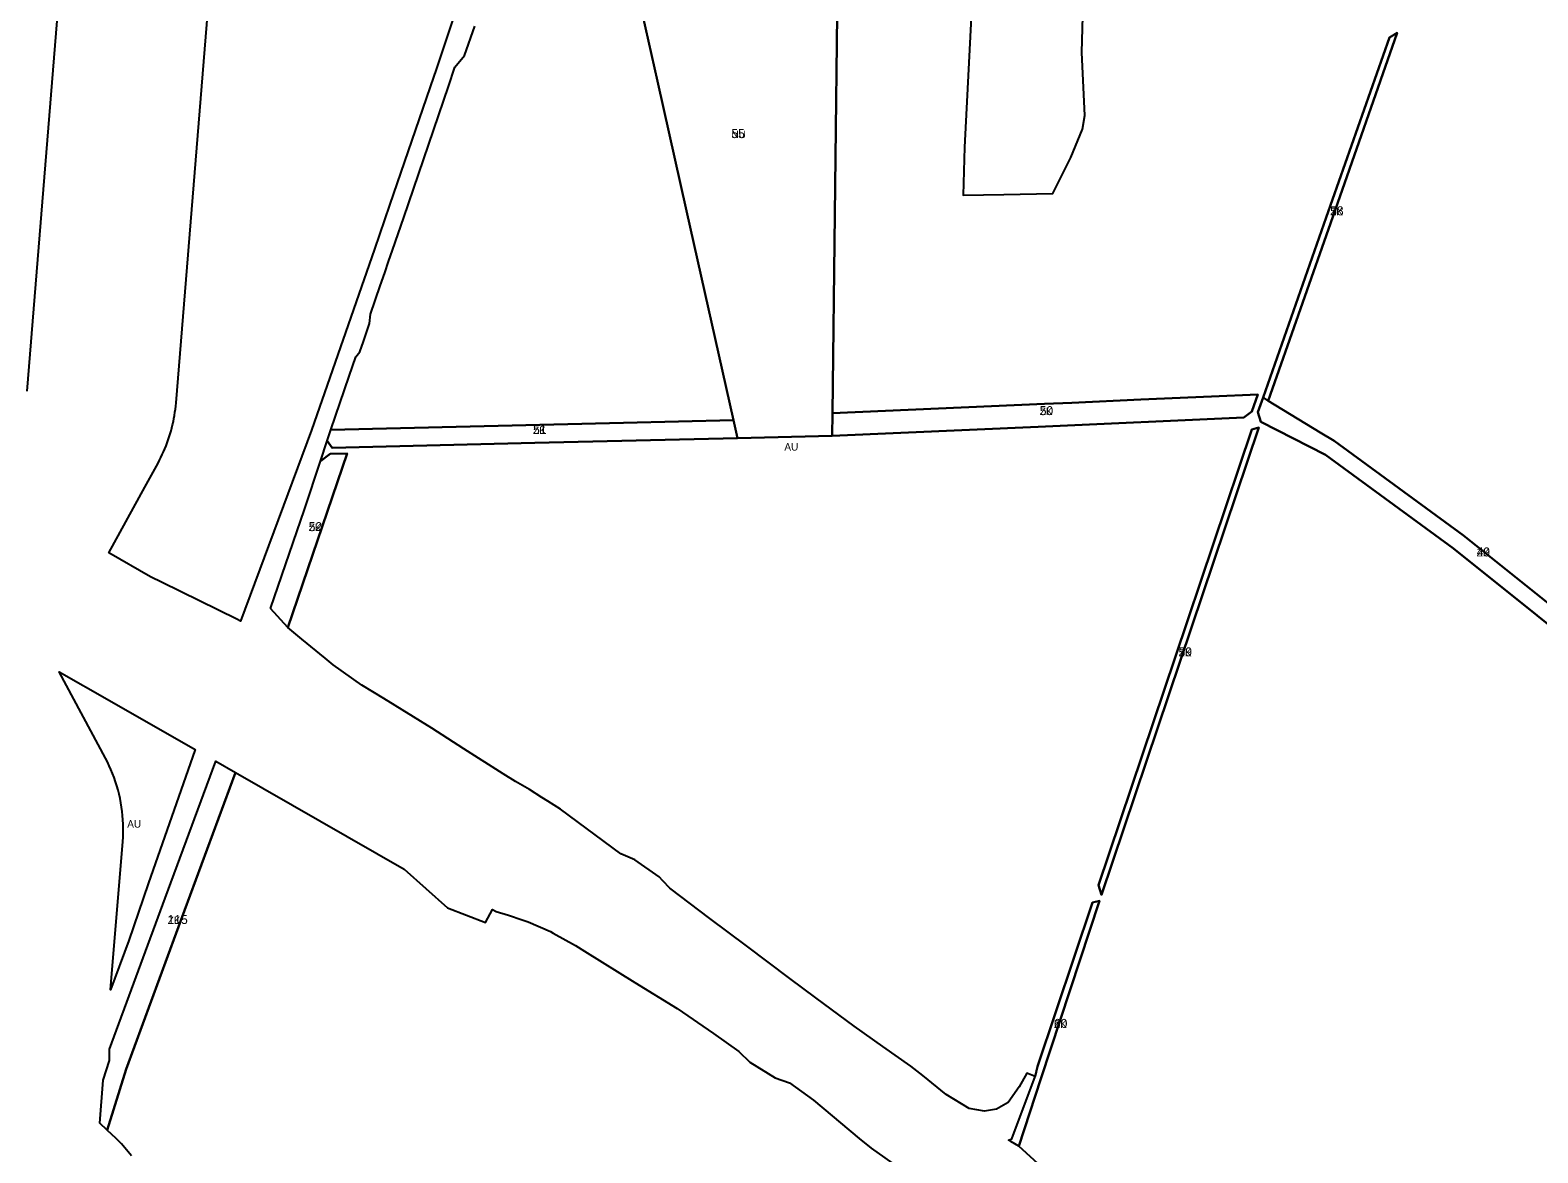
# Model space of a CAD drawing. Extents: x -545779 to -541342, y -1153413 to -1149956.
# Drawn here: x -544840 to -543834, y -1152759 to -1152010 of the extents above; entities that cross this region are included whole.
import ezdxf

# ---------------------------------------------------------------- set-up
doc = ezdxf.new("R2010")
doc.units = 0
for name, color, linetype in [('90710023', 7, 'Continuous'), ('90730023', 7, 'Continuous'), ('90750013', 7, 'Continuous'), ('ID_navrh', 7, 'Continuous')]:
    doc.layers.add(name, color=color, linetype=linetype)

msp = doc.modelspace()

# ---------------------------------------------------------------- linework, layer by layer
at = {"layer": '90710023'}
for points in [[(-543974.76, -1152134.86), (-543974.76, -1152134.86), (-543932.62, -1152014.61), (-543927.33, -1152011.63), (-543970.37, -1152134.42), (-544013.41, -1152257.22), (-544016.91, -1152255.1)], [(-544167.08, -1152274.5), (-544167.08, -1152274.5), (-544304.43, -1152280.58), (-544304.26, -1152265.56), (-544162.8, -1152259.29), (-544144.44, -1152258.48), (-544098.47, -1152256.44), (-544051.35, -1152254.35), (-544020.4, -1152252.98), (-544024.42, -1152264.45), (-544029.74, -1152268.41)], [(-544502.79, -1152285.35), (-544638.01, -1152288.6), (-544641.43, -1152283.98), (-544638.99, -1152276.62), (-544443.74, -1152271.92), (-544370.25, -1152270.16), (-544367.57, -1152282.1)], [(-544075.6, -1152428.52), (-544024.37, -1152276.35), (-544019.71, -1152275.05), (-544072.24, -1152431.07), (-544124.76, -1152587.09), (-544126.82, -1152580.69)], [(-544679.3, -1152395.86), (-544656.61, -1152329.75), (-544645.92, -1152297.5), (-544639.34, -1152292.63), (-544628.21, -1152292.37), (-544667.8, -1152408.57)], [(-544790.854, -1152710.719), (-544786.64, -1152697.75), (-544786.7, -1152690.05), (-544749.46, -1152589.25), (-544715.712, -1152497.902), (-544702.513, -1152505.459), (-544736.56, -1152597.62), (-544775.66, -1152703.45), (-544788.338, -1152744.096), (-544793.194, -1152739.453)], [(-544167.53, -1152701.6), (-544130.71, -1152592.24), (-544126.11, -1152591.11), (-544165.26, -1152709.92), (-544179.87, -1152754.91), (-544185.3, -1152751.8), (-544186.78, -1152750.95), (-544184.48, -1152749.94), (-544168.92, -1152708.47)]]:
    msp.add_lwpolyline(points, close=True, dxfattribs=at)
msp.add_lwpolyline([(-543778.21, -1152445.38), (-543889.81, -1152355.78), (-543975.36, -1152293.26), (-544018.36, -1152271.25), (-544020.31, -1152264.83), (-544016.91, -1152255.1), (-544013.41, -1152257.22), (-543978.75, -1152278.28), (-543969.58, -1152283.87), (-543883.11, -1152347.05), (-543856.48, -1152368.44), (-543813.2, -1152403.19)], dxfattribs=at)
at = {"layer": '90730023'}
msp.add_lwpolyline([(-544335.32, -1151922.05), (-544325.42, -1151928.09), (-544321.27, -1151930.63), (-544306.99, -1151939.34), (-544300.59, -1151943.25), (-544300.75, -1151957.52), (-544300.79, -1151961.28), (-544302.75, -1152132.72), (-544304.26, -1152265.56), (-544304.43, -1152280.58), (-544367.57, -1152282.1), (-544370.25, -1152270.16), (-544401.66, -1152130.3), (-544421.06, -1152043.91), (-544421.06, -1152043.91), (-544433.09, -1151990.35), (-544442.21, -1151949.72), (-544442.79, -1151947.17), (-544440.77, -1151943.22), (-544407.5, -1151878.02), (-544351.13, -1151912.42), (-544338.6, -1151920.06)], close=True, dxfattribs=at)
at = {"layer": '90750013'}
for points in [[(-544863.56, -1151471.74), (-544835.58, -1151476.61), (-544829.76, -1151477.63), (-544817.04, -1151478.48), (-544806.75, -1151479.17), (-544784.41, -1151478.6), (-544779.283, -1151478.465), (-544841.973, -1152250.685)], [(-544535.68, -1151936.25), (-544569.04, -1152036.59), (-544570.31, -1152040.39), (-544599.8, -1152126.71), (-544609.92, -1152155.93), (-544651.83, -1152276.93), (-544699.22, -1152404.28), (-544701.77, -1152403.03), (-544751.588, -1152378.627), (-544759.32, -1152374.84), (-544787.104, -1152358.82), (-544763.152, -1152314.985), (-544754.3, -1152298.784), (-544753.313, -1152296.931), (-544752.363, -1152295.055), (-544751.45, -1152293.156), (-544750.576, -1152291.236), (-544749.742, -1152289.295), (-544748.947, -1152287.335), (-544748.193, -1152285.357), (-544747.481, -1152283.362), (-544746.81, -1152281.352), (-544746.181, -1152279.327), (-544745.595, -1152277.29), (-544745.053, -1152275.241), (-544744.553, -1152273.183), (-544744.098, -1152271.115), (-544743.686, -1152269.041), (-544743.318, -1152266.96), (-544742.994, -1152264.875), (-544742.714, -1152262.787), (-544742.479, -1152260.697), (-544742.287, -1152258.607), (-544678.286, -1151470.229)], [(-544156.94, -1152775.87), (-544179.87, -1152754.91), (-544165.26, -1152709.92), (-544126.11, -1152591.11), (-544130.71, -1152592.24), (-544167.53, -1152701.6), (-544168.92, -1152708.47), (-544174.58, -1152706.23), (-544179.65, -1152715.2), (-544187.06, -1152725.65), (-544194.85, -1152730.16), (-544202.82, -1152731.45), (-544212.95, -1152729.77), (-544228.42, -1152720.47), (-544243.97, -1152707.66), (-544251.88, -1152701.53), (-544270.61, -1152688.32), (-544289.81, -1152674.78), (-544315.46, -1152655.76), (-544332.78, -1152642.83), (-544361.7, -1152621.09), (-544386.07, -1152602.77), (-544412.68, -1152582.66), (-544417.46, -1152577.62), (-544419.8, -1152575.16), (-544436.22, -1152563.74), (-544445.52, -1152559.63), (-544485.69, -1152529.96), (-544494.22, -1152524.49), (-544498.11, -1152522), (-544506.5, -1152516.81), (-544515.72, -1152511.34), (-544523.97, -1152506.3), (-544550.16, -1152489.69), (-544571.54, -1152475.88), (-544603.68, -1152456.06), (-544618.29, -1152447.13), (-544637.45, -1152433.53), (-544642.8, -1152429.13), (-544658.35, -1152416.34), (-544667.8, -1152408.57), (-544628.21, -1152292.37), (-544639.34, -1152292.63), (-544645.92, -1152297.5), (-544641.43, -1152283.98), (-544638.01, -1152288.6), (-544502.79, -1152285.35), (-544367.57, -1152282.1), (-544304.43, -1152280.58), (-544167.08, -1152274.5), (-544029.74, -1152268.41), (-544024.42, -1152264.45), (-544020.4, -1152252.98), (-544051.35, -1152254.35), (-544098.47, -1152256.44), (-544144.44, -1152258.48), (-544162.8, -1152259.29), (-544304.26, -1152265.56), (-544302.75, -1152132.72), (-544300.79, -1151961.28)], [(-544433.09, -1151990.35), (-544421.06, -1152043.91), (-544421.06, -1152043.91), (-544401.66, -1152130.3), (-544370.25, -1152270.16), (-544443.74, -1152271.92), (-544638.99, -1152276.62), (-544626.78, -1152240.84), (-544622.37, -1152227.91), (-544619.66, -1152224.61), (-544617.23, -1152217.55), (-544613.15, -1152205.7), (-544612.56, -1152199.38), (-544606, -1152180.35), (-544603.03, -1152171.72), (-544600.43, -1152164.15), (-544597.88, -1152156.75), (-544590.33, -1152134.84), (-544560.42, -1152047.27), (-544556.17, -1152034.56), (-544549.76, -1152026.71), (-544543.02, -1152007.12)], [(-543813.2, -1152403.19), (-543856.48, -1152368.44), (-543883.11, -1152347.05), (-543969.58, -1152283.87), (-543978.75, -1152278.28), (-544013.41, -1152257.22), (-543970.37, -1152134.42), (-543927.33, -1152011.63), (-543932.62, -1152014.61), (-543974.76, -1152134.86), (-544016.91, -1152255.1), (-544020.31, -1152264.83), (-544018.36, -1152271.25), (-543975.36, -1152293.26), (-543889.81, -1152355.78), (-543778.21, -1152445.38)], [(-544772.057, -1152761.29), (-544775.324, -1152757.255), (-544778.755, -1152753.436), (-544782.332, -1152749.839), (-544788.338, -1152744.096), (-544775.66, -1152703.45), (-544736.56, -1152597.62), (-544702.513, -1152505.459), (-544590.019, -1152569.865), (-544561.127, -1152595.796), (-544535.811, -1152605.485), (-544531.193, -1152596.854), (-544528.77, -1152598.15), (-544520.47, -1152600.54), (-544511.43, -1152603.7), (-544507.3, -1152605.14), (-544492.33, -1152611.64), (-544490.57, -1152612.64), (-544475.81, -1152621.01), (-544469.8, -1152624.74), (-544436.09, -1152645.61), (-544407.8, -1152662.87), (-544383.71, -1152679.75), (-544366.83, -1152691.57), (-544359.49, -1152698.7), (-544342.45, -1152709.16), (-544332.96, -1152712.61), (-544316.92, -1152724.14), (-544286.46, -1152749.87), (-544278.41, -1152756.13), (-544245.81, -1152779.45)]]:
    msp.add_lwpolyline(points, dxfattribs=at)
for points in [[(-544216.21, -1152087.96), (-544217.12, -1152120.01), (-544189.83, -1152119.54), (-544157.13, -1152118.8), (-544145.23, -1152094.69), (-544137.48, -1152075.92), (-544135.77, -1152066.84), (-544137.89, -1152024.68), (-544137.24, -1152000.5), (-544137.3, -1151975.86), (-544137.32, -1151968.36), (-544139.1, -1151968.37), (-544142.54, -1151967.58), (-544179.69, -1151968.08), (-544210.18, -1151967.43), (-544211.7, -1152001)], [(-544024.37, -1152276.35), (-544075.6, -1152428.52), (-544126.82, -1152580.69), (-544124.76, -1152587.09), (-544072.24, -1152431.07), (-544019.71, -1152275.05)], [(-544773.83, -1152617.6), (-544785.958, -1152650.605), (-544777.879, -1152551.404), (-544777.688, -1152548.564), (-544777.577, -1152545.709), (-544777.547, -1152542.843), (-544777.599, -1152539.969), (-544777.733, -1152537.091), (-544777.95, -1152534.212), (-544778.249, -1152531.335), (-544778.632, -1152528.465), (-544779.098, -1152525.604), (-544779.645, -1152522.757), (-544780.275, -1152519.927), (-544780.985, -1152517.117), (-544781.775, -1152514.331), (-544782.644, -1152511.572), (-544783.589, -1152508.844), (-544784.611, -1152506.15), (-544785.706, -1152503.492), (-544786.873, -1152500.874), (-544788.11, -1152498.299), (-544789.414, -1152495.769), (-544820.193, -1152438.084), (-544786.656, -1152457.285), (-544729.515, -1152490), (-544760.95, -1152579.73)]]:
    msp.add_lwpolyline(points, close=True, dxfattribs=at)

# ---------------------------------------------------------------- texts
at = {"layer": '90710023'}
for p in [(-543972.12, -1152133.37), (-544165.912, -1152266.78), (-544504.043, -1152279.38), (-543874.364, -1152361.13), (-544073.265, -1152427.85), (-544747.854, -1152606.545), (-544156.445, -1152675.922)]:
    msp.add_text('ZK', height=5, rotation=0, dxfattribs=at).set_placement(p)
msp.add_text('ZK', height=5, dxfattribs=at).set_placement((-544653.755, -1152344.242))
at = {"layer": '90730023'}
msp.add_text('NU', height=5, rotation=360, dxfattribs=at).set_placement((-544371.69, -1152081.811))
at = {"layer": '90750013'}
for rotation, p in [(360, (-544336.358, -1152290.48)), (0, (-544774.854, -1152542.214))]:
    msp.add_text('AU', height=5, rotation=rotation, dxfattribs=at).set_placement(p)
at = {"layer": 'ID_navrh'}
for s, rotation, p in [('55', 360, (-544371.69, -1152081.811)), ('58', 0, (-543972.12, -1152133.37)), ('50', 0, (-544165.912, -1152266.78)), ('51', 360, (-544504.043, -1152279.38)), ('52', 0, (-544653.755, -1152344.242)), ('49', 0, (-543874.364, -1152361.13)), ('59', 0, (-544073.265, -1152427.85)), ('115', 0, (-544747.854, -1152606.545)), ('60', 0, (-544156.445, -1152675.922))]:
    msp.add_text(s, height=6, rotation=rotation, dxfattribs=at).set_placement(p)

doc.saveas('drawing.dxf')
